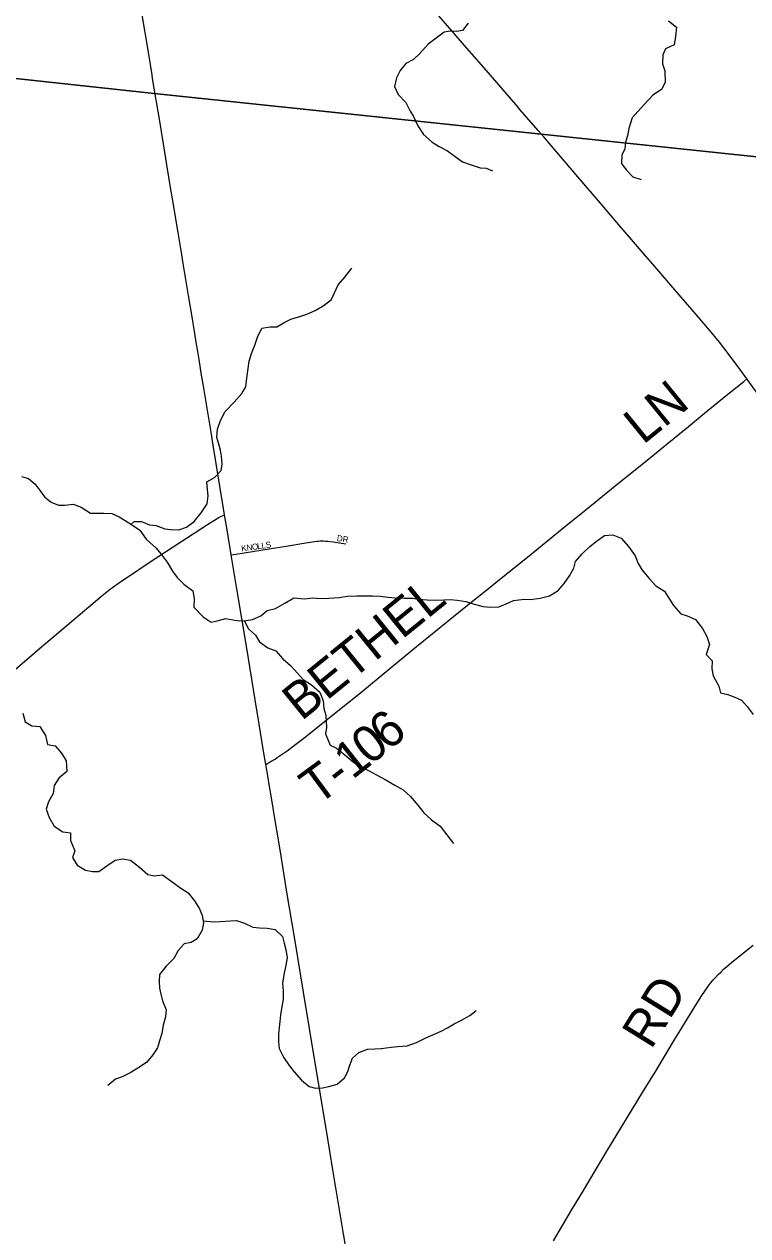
# Model space of a CAD drawing. Extents: x 1442749 to 1756758, y 235267 to 677782.
# Drawn here: x 1597135 to 1603104, y 500562 to 510563 of the extents above; entities that cross this region are included whole.
import ezdxf

# ---------------------------------------------------------------- set-up
doc = ezdxf.new("R2010")
doc.units = 0
for name, color, linetype in [('GM_X_County_Road', 7, 'Continuous'), ('GM_X_County_Road_Text', 7, 'Continuous'), ('GM_X_Minor_River', 7, 'Continuous'), ('GM_X_State_Route', 7, 'Continuous'), ('GM_X_Township', 7, 'Continuous'), ('GM_X_Township_Road', 7, 'Continuous'), ('GM_X_Township_Road_Text', 7, 'Continuous'), ('GM_X_Township_Subdivision', 7, 'Continuous'), ('GM_X_Township_Subdivision_Text', 7, 'Continuous')]:
    doc.layers.add(name, color=color, linetype=linetype)

msp = doc.modelspace()

# ---------------------------------------------------------------- linework, layer by layer
at = {"layer": 'GM_X_County_Road'}
for points in [[(1601222, 509863), (1601206, 509881), (1600981, 510142), (1600888, 510249), (1600767, 510387), (1600664, 510506), (1600462, 510739), (1600219, 511019), (1600134, 511114), (1600058, 511196), (1599917, 511343), (1599750, 511514), (1599602, 511668), (1599544, 511726), (1599525, 511744), (1599508, 511760), (1599493, 511772), (1599479, 511782), (1599466, 511791), (1599452, 511801), (1599447, 511803)], [(1601377, 509682), (1601222, 509863)], [(1603096, 507636), (1603046, 507704), (1602959, 507823), (1602871, 507938), (1602819, 508002), (1602695, 508147), (1602485, 508389), (1602338, 508562), (1602243, 508671), (1602145, 508785), (1602023, 508927), (1601903, 509070), (1601701, 509304), (1601418, 509635), (1601377, 509682)], [(1605250, 505137), (1605226, 505164), (1605116, 505285), (1604924, 505501), (1604730, 505724), (1604615, 505853), (1604471, 506020), (1604275, 506241), (1604109, 506431), (1603708, 506891), (1603463, 507174), (1603333, 507325), (1603283, 507386), (1603234, 507448), (1603153, 507555), (1603096, 507636)], [(1596940, 505133), (1597280, 505427), (1597381, 505511), (1597632, 505722), (1597774, 505844), (1597830, 505888), (1597846, 505901), (1597864, 505914), (1597885, 505930), (1597901, 505942), (1597924, 505958), (1597961, 505983), (1598190, 506136), (1598647, 506433), (1598727, 506484), (1598738, 506490), (1598751, 506496), (1598787, 506513)], [(1601501, 500521), (1601651, 500772), (1601748, 500935), (1601941, 501259), (1602235, 501744), (1602347, 501926), (1602495, 502170), (1602649, 502422), (1602720, 502536), (1602754, 502589), (1602768, 502609), (1602785, 502632), (1602800, 502651), (1602817, 502673), (1602838, 502695), (1602859, 502719), (1602881, 502739), (1602905, 502762), (1602928, 502782), (1602973, 502819), (1603148, 502962)]]:
    msp.add_lwpolyline(points, dxfattribs=at)
at = {"layer": 'GM_X_Minor_River'}
for points in [[(1600797, 510573), (1600750, 510511), (1600700, 510504), (1600650, 510506), (1600598, 510497), (1600533, 510449), (1600467, 510398), (1600395, 510319), (1600345, 510271), (1600284, 510238), (1600235, 510180), (1600207, 510120), (1600190, 510050), (1600221, 509984), (1600282, 509917), (1600316, 509852), (1600347, 509800), (1600382, 509725), (1600430, 509652), (1600501, 509589), (1600557, 509555), (1600626, 509518), (1600680, 509479), (1600750, 509426), (1600821, 509401), (1600895, 509378), (1600947, 509376), (1600999, 509353)], [(1602451, 510592), (1602517, 510539), (1602508, 510463), (1602497, 510393), (1602426, 510361), (1602402, 510310), (1602401, 510237), (1602420, 510177), (1602423, 510081), (1602392, 510023), (1602321, 509978), (1602252, 509902), (1602196, 509843), (1602151, 509791), (1602124, 509703), (1602113, 509641), (1602096, 509589), (1602090, 509535), (1602065, 509481), (1602062, 509413), (1602102, 509362), (1602155, 509304), (1602225, 509281)], [(1598016, 506436), (1598041, 506459), (1598103, 506458), (1598169, 506431), (1598223, 506424), (1598294, 506398), (1598344, 506393), (1598411, 506388), (1598473, 506412), (1598536, 506459), (1598595, 506530), (1598644, 506604), (1598652, 506670), (1598647, 506722), (1598642, 506785), (1598706, 506820), (1598759, 506878), (1598768, 506932), (1598762, 506996), (1598753, 507046), (1598740, 507096), (1598724, 507151), (1598729, 507221), (1598754, 507291), (1598793, 507367), (1598866, 507442), (1598931, 507515), (1598962, 507569), (1598970, 507619), (1598979, 507701), (1598992, 507782), (1599009, 507846), (1599038, 507915), (1599059, 507981), (1599096, 508053), (1599164, 508064), (1599220, 508066), (1599285, 508103), (1599335, 508129), (1599416, 508152), (1599466, 508169), (1599534, 508200), (1599601, 508238), (1599666, 508289), (1599695, 508347), (1599725, 508413), (1599780, 508476), (1599839, 508548)], [(1597113, 506830), (1597171, 506812), (1597225, 506765), (1597266, 506712), (1597303, 506662), (1597357, 506617), (1597417, 506594), (1597471, 506594), (1597539, 506601), (1597605, 506576), (1597681, 506527), (1597731, 506526), (1597791, 506528), (1597857, 506523), (1597917, 506496), (1597969, 506465), (1598036, 506423), (1598088, 506386), (1598141, 506313), (1598220, 506240), (1598266, 506187), (1598313, 506121), (1598358, 506048), (1598398, 505995), (1598451, 505940), (1598525, 505885), (1598536, 505823), (1598533, 505751), (1598610, 505672), (1598678, 505627), (1598728, 505638)], [(1598728, 505638), (1598799, 505656), (1598855, 505645), (1598907, 505638), (1598965, 505642), (1599017, 505649), (1599088, 505680), (1599138, 505722), (1599208, 505739), (1599285, 505784), (1599358, 505828), (1599444, 505821), (1599516, 505828), (1599576, 505823), (1599648, 505826), (1599733, 505831), (1599801, 505841), (1599879, 505844), (1599949, 505845), (1600009, 505844), (1600070, 505842), (1600138, 505833), (1600198, 505828), (1600268, 505825), (1600338, 505824), (1600388, 505818), (1600460, 505811), (1600530, 505810), (1600596, 505812), (1600648, 505813), (1600706, 505810), (1600779, 505797), (1600846, 505775), (1600922, 505756), (1600982, 505751), (1601051, 505754), (1601105, 505776), (1601171, 505805), (1601258, 505816), (1601312, 505815), (1601392, 505824), (1601469, 505844), (1601539, 505889), (1601588, 505945), (1601633, 506010), (1601670, 506072), (1601684, 506128), (1601737, 506192), (1601802, 506253), (1601863, 506300), (1601921, 506342), (1601990, 506347), (1602059, 506320), (1602119, 506253), (1602174, 506174), (1602201, 506112), (1602233, 506057), (1602290, 505987), (1602345, 505928), (1602417, 505883), (1602458, 505818), (1602490, 505764), (1602551, 505697), (1602605, 505680), (1602673, 505649), (1602730, 505576), (1602767, 505510), (1602789, 505443), (1602762, 505361), (1602811, 505307), (1602808, 505241), (1602818, 505184), (1602865, 505099), (1602880, 505045), (1602940, 505030), (1602998, 505008), (1603052, 504983), (1603099, 504932), (1603148, 504864)], [(1598949, 505641), (1598986, 505571), (1599042, 505520), (1599077, 505464), (1599144, 505415), (1599212, 505390), (1599268, 505325), (1599331, 505268), (1599389, 505206), (1599436, 505153), (1599504, 505110), (1599573, 505049), (1599600, 504977), (1599608, 504914), (1599623, 504860), (1599630, 504758), (1599621, 504706), (1599660, 504613), (1599712, 504588), (1599781, 504533), (1599851, 504470), (1599910, 504433), (1599976, 504403), (1600036, 504370), (1600112, 504329), (1600193, 504282), (1600261, 504243), (1600318, 504190), (1600382, 504117), (1600431, 504054), (1600496, 503995), (1600566, 503943), (1600677, 503801)], [(1597124, 504875), (1597143, 504804), (1597197, 504772), (1597265, 504767), (1597310, 504692), (1597327, 504618), (1597391, 504605), (1597443, 504546), (1597480, 504481), (1597487, 504393), (1597420, 504340), (1597383, 504278), (1597374, 504214), (1597334, 504144), (1597317, 504082), (1597340, 504014), (1597381, 503943), (1597453, 503896), (1597517, 503889), (1597518, 503825), (1597553, 503740), (1597532, 503683)], [(1597532, 503683), (1597572, 503622), (1597641, 503579), (1597699, 503568), (1597750, 503570), (1597816, 503615), (1597885, 503662), (1597949, 503674), (1598013, 503661), (1598087, 503604), (1598156, 503543), (1598208, 503532), (1598276, 503540), (1598344, 503491)], [(1598344, 503491), (1598428, 503432), (1598488, 503393), (1598541, 503327), (1598580, 503260), (1598603, 503205), (1598615, 503145), (1598602, 503085), (1598563, 503014), (1598512, 502982), (1598454, 502971), (1598405, 502917), (1598370, 502850), (1598307, 502786), (1598250, 502719), (1598249, 502661), (1598252, 502607), (1598262, 502555), (1598277, 502500), (1598306, 502428), (1598301, 502370), (1598280, 502300), (1598269, 502232), (1598252, 502170), (1598234, 502112), (1598197, 502054), (1598144, 501991), (1598081, 501950), (1598014, 501910), (1597944, 501875), (1597889, 501854), (1597824, 501801)], [(1598611, 503162), (1598697, 503154), (1598751, 503157), (1598837, 503162), (1598887, 503164), (1598953, 503143), (1599021, 503110), (1599077, 503103), (1599139, 503100), (1599205, 503089), (1599267, 503031), (1599280, 502976), (1599293, 502924), (1599304, 502856), (1599292, 502796), (1599277, 502716), (1599266, 502648), (1599271, 502582), (1599270, 502513), (1599261, 502453), (1599250, 502385), (1599243, 502331), (1599239, 502281), (1599234, 502225), (1599233, 502163), (1599238, 502107), (1599273, 502036), (1599321, 501968), (1599362, 501915), (1599423, 501846), (1599487, 501795), (1599539, 501780), (1599595, 501784), (1599647, 501793), (1599718, 501812), (1599776, 501865), (1599805, 501919), (1599822, 501971), (1599843, 502029), (1599896, 502076), (1599968, 502101), (1600028, 502105), (1600079, 502108), (1600163, 502119), (1600217, 502124), (1600293, 502131), (1600370, 502156), (1600443, 502192), (1600574, 502250), (1600626, 502279), (1600681, 502311), (1600741, 502342), (1600812, 502381), (1600863, 502421)]]:
    msp.add_lwpolyline(points, dxfattribs=at)
at = {"layer": 'GM_X_State_Route'}
msp.add_lwpolyline([(1599856, 500053), (1599768, 500577), (1599681, 501105), (1599631, 501415), (1599538, 501972), (1599438, 502574), (1599367, 503011), (1599302, 503399), (1599257, 503678), (1599222, 503895), (1599219, 503911), (1599217, 503924), (1599166, 504227), (1599164, 504241), (1599162, 504253), (1599141, 504376), (1599128, 504453), (1599110, 504561), (1599074, 504784), (1599041, 504985), (1598971, 505412), (1598890, 505901), (1598843, 506183), (1598834, 506234), (1598806, 506406), (1598787, 506513), (1598779, 506564), (1598749, 506749), (1598695, 507089), (1598678, 507196), (1598610, 507593), (1598598, 507667), (1598586, 507739), (1598577, 507794), (1598566, 507861), (1598554, 507937), (1598542, 508011), (1598517, 508163), (1598491, 508325), (1598446, 508587), (1598430, 508694), (1598402, 508859), (1598386, 508956), (1598369, 509057), (1598340, 509231), (1598256, 509746), (1598194, 510115), (1598190, 510145), (1598162, 510316), (1598100, 510691)], dxfattribs=at)
at = {"layer": 'GM_X_Township'}
for points in [[(1607409, 509023), (1601349, 509660), (1598207, 509991), (1595438, 510291), (1595355, 510300), (1591670, 510701), (1587291, 511156), (1584741, 511410), (1583705, 511521), (1580873, 511825), (1577466, 512312), (1577336, 518378), (1577247, 522507)], [(1573762, 498986), (1574679, 502300), (1575144, 503972), (1577400, 512074), (1577466, 512312), (1580873, 511825), (1583705, 511521), (1584741, 511410), (1587291, 511156), (1591670, 510701), (1595355, 510300), (1595438, 510291), (1598207, 509991), (1601349, 509660), (1607409, 509023), (1609267, 508822), (1609586, 508788), (1610595, 504741), (1611751, 500101)]]:
    msp.add_lwpolyline(points, dxfattribs=at)
at = {"layer": 'GM_X_Township_Road'}
msp.add_lwpolyline([(1599128, 504453), (1599164, 504473), (1599190, 504487), (1599205, 504497), (1599223, 504509), (1599303, 504565), (1599388, 504627), (1599442, 504669), (1599641, 504830), (1599803, 504959), (1599895, 505033), (1600072, 505179), (1600167, 505259), (1600370, 505426), (1600530, 505556), (1600777, 505756), (1600952, 505895), (1601070, 505989), (1601287, 506163), (1601467, 506312), (1601602, 506421), (1601771, 506556), (1602009, 506752), (1602273, 506964), (1602438, 507098), (1602599, 507228), (1602748, 507351), (1602926, 507497), (1603071, 507615), (1603096, 507636)], dxfattribs=at)
at = {"layer": 'GM_X_Township_Subdivision'}
msp.add_lwpolyline([(1598843, 506183), (1598880, 506188), (1599155, 506232), (1599297, 506255), (1599459, 506282), (1599550, 506296), (1599563, 506297), (1599576, 506298), (1599590, 506299), (1599605, 506298), (1599621, 506297), (1599638, 506296), (1599684, 506291), (1599788, 506274)], dxfattribs=at)

# ---------------------------------------------------------------- texts
at = {"layer": 'GM_X_County_Road_Text'}
msp.add_text('RD', height=300, rotation=58.2003, dxfattribs=at).set_placement((1602306, 502092))
at = {"layer": 'GM_X_Township_Road_Text'}
for s, rotation, p in [('LN', 39.1433, (1602240, 507087)), ('BETHEL', 39.1033, (1599422, 504806)), ('6', 39.3747, (1600135, 504557)), ('0', 38.556, (1599987, 504439)), ('1', 38.4111, (1599842, 504323)), ('T', 36.3882, (1599554, 504108)), ('-', 37.6307, (1599741, 504245))]:
    msp.add_text(s, height=300, rotation=rotation, dxfattribs=at).set_placement(p)
at = {"layer": 'GM_X_Township_Subdivision_Text'}
for s, rotation, p in [('K', 7.8705, (1598929, 506210)), ('N', 7.8617, (1598973, 506216)), ('O', 7.8705, (1599017, 506222)), ('L', 7.8502, (1599060, 506228)), ('L', 7.862, (1599095, 506233)), ('S', 8.9793, (1599131, 506238)), ('DR', 350.5318, (1599711, 506298))]:
    msp.add_text(s, height=50, rotation=rotation, dxfattribs=at).set_placement(p)

doc.saveas('drawing.dxf')
